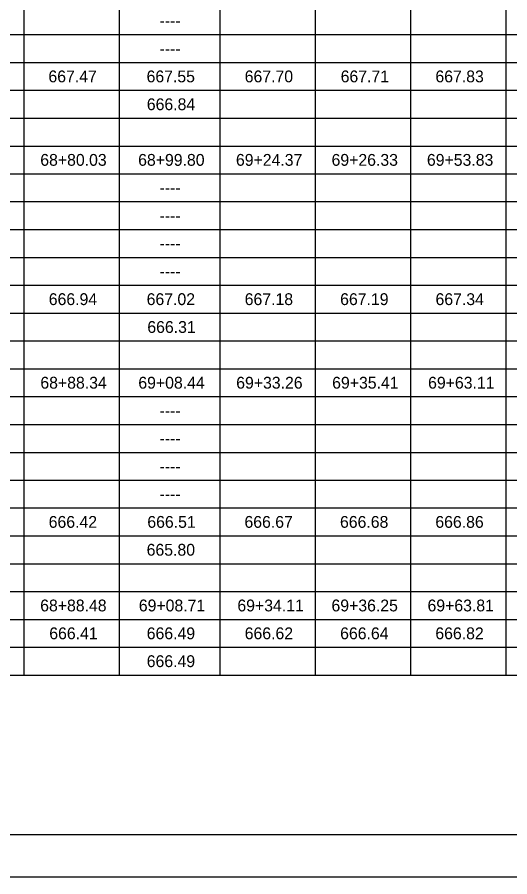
# Model space of a CAD drawing. Extents: x 0 to 34, y 0 to 22.
# Drawn here: x 19.14 to 24.99, y 0 to 10.21 of the extents above; entities that cross this region are included whole.
import ezdxf

# ---------------------------------------------------------------- set-up
doc = ezdxf.new("R2010")
doc.units = 0
for name, color, linetype in [('SH_Border', 7, 'Continuous'), ('SH_Cut_Line', 7, 'Continuous'), ('SH_Text', 7, 'Continuous')]:
    doc.layers.add(name, color=color, linetype=linetype)

msp = doc.modelspace()

# ---------------------------------------------------------------- linework, layer by layer
at = {"layer": 'SH_Border'}
msp.add_lwpolyline([(1.5, 21.5), (33.5, 21.5), (33.5, 0.5), (1.5, 0.5)], close=True, dxfattribs=at)
at = {"layer": 'SH_Cut_Line'}
msp.add_lwpolyline([(0, 0), (34, 0), (34, 22), (0, 22)], close=True, dxfattribs=at)
at = {"layer": 'SH_Text'}
for p, q in [((19.218, 20.113), (19.218, 2.397)), ((20.351, 20.113), (20.351, 2.397)), ((21.547, 20.113), (21.547, 2.397)), ((22.68, 20.113), (22.68, 2.397)), ((23.813, 20.113), (23.813, 2.397)), ((24.945, 20.113), (24.945, 2.397)), ((4.2, 10.008), (30.673, 10.008)), ((4.2, 9.677), (30.673, 9.677)), ((4.2, 9.346), (30.673, 9.346)), ((2.8, 9.015), (30.673, 9.015)), ((2.8, 8.684), (30.673, 8.684)), ((4.2, 8.353), (30.673, 8.353)), ((4.2, 8.023), (30.673, 8.023)), ((4.2, 7.692), (30.673, 7.692)), ((4.2, 7.361), (30.673, 7.361)), ((4.2, 7.03), (30.673, 7.03)), ((4.2, 6.699), (30.673, 6.699)), ((2.8, 6.368), (30.673, 6.368)), ((2.8, 6.037), (30.673, 6.037)), ((4.2, 5.706), (30.673, 5.706)), ((4.2, 5.375), (30.673, 5.375)), ((4.2, 5.044), (30.673, 5.044)), ((4.2, 4.713), (30.673, 4.713)), ((4.2, 4.383), (30.673, 4.383)), ((4.2, 4.052), (30.673, 4.052)), ((2.8, 3.721), (30.673, 3.721)), ((2.8, 3.39), (30.673, 3.39)), ((4.2, 3.059), (30.673, 3.059)), ((4.2, 2.728), (30.673, 2.728)), ((2.8, 2.397), (30.673, 2.397))]:
    msp.add_line(p, q, dxfattribs=at)

# ---------------------------------------------------------------- texts
for s, p in [('----', (20.831, 10.103)), ('----', (20.831, 9.772)), ('667.47', (19.511, 9.441)), ('667.55', (20.677, 9.441)), ('667.70', (21.843, 9.441)), ('667.71', (22.983, 9.441)), ('667.83', (24.109, 9.441)), ('666.84', (20.68, 9.11)), ('68+80.03', (19.414, 8.449)), ('68+99.80', (20.577, 8.449)), ('69+24.37', (21.739, 8.449)), ('69+26.33', (22.875, 8.449)), ('69+53.83', (24.008, 8.449)), ('----', (20.831, 8.118)), ('----', (20.831, 7.787)), ('----', (20.831, 7.456)), ('----', (20.831, 7.125)), ('666.94', (19.515, 6.794)), ('667.02', (20.678, 6.794)), ('667.18', (21.843, 6.794)), ('667.19', (22.977, 6.794)), ('667.34', (24.11, 6.794)), ('666.31', (20.686, 6.463)), ('68+88.34', (19.415, 5.801)), ('69+08.44', (20.579, 5.801)), ('69+33.26', (21.742, 5.801)), ('69+35.41', (22.882, 5.801)), ('69+63.11', (24.022, 5.801)), ('----', (20.831, 5.47)), ('----', (20.831, 5.14)), ('----', (20.831, 4.809)), ('----', (20.831, 4.478)), ('666.42', (19.514, 4.147)), ('666.51', (20.686, 4.147)), ('666.67', (21.84, 4.147)), ('666.68', (22.975, 4.147)), ('666.86', (24.108, 4.147)), ('665.80', (20.678, 3.816)), ('68+88.48', (19.413, 3.154)), ('69+08.71', (20.585, 3.154)), ('69+34.11', (21.756, 3.154)), ('69+36.25', (22.874, 3.154)), ('69+63.81', (24.015, 3.154)), ('666.41', (19.521, 2.823)), ('666.49', (20.679, 2.823)), ('666.62', (21.843, 2.823)), ('666.64', (22.977, 2.823)), ('666.82', (24.108, 2.823)), ('666.49', (20.679, 2.492))]:
    msp.add_text(s, height=0.1405, dxfattribs=at).set_placement(p)

doc.saveas('drawing.dxf')
